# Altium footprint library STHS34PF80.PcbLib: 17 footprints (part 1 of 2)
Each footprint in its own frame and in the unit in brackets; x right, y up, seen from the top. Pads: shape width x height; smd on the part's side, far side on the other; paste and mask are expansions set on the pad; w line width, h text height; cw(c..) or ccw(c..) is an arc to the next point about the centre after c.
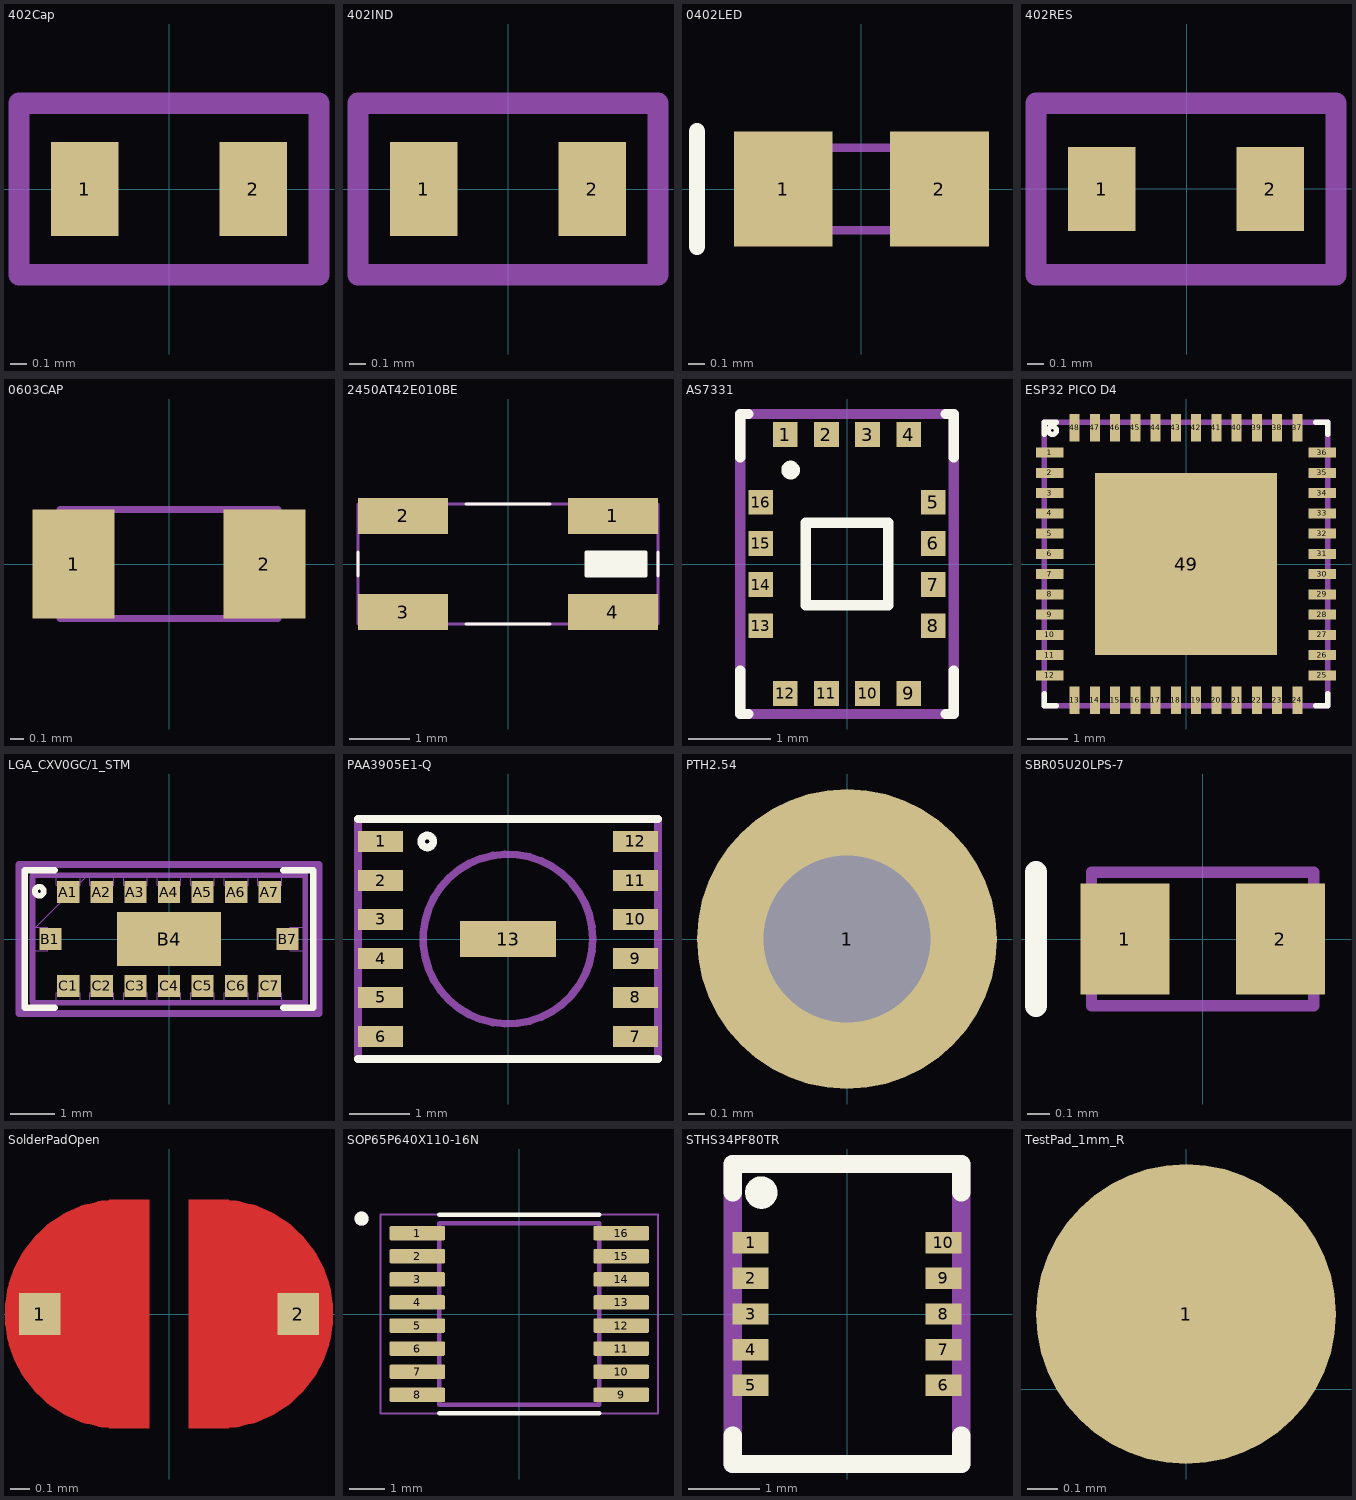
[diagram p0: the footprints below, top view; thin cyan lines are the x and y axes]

## 402Cap [mm] "0402 package capacitor"
pads (2):
  rect 0.4x0.559 smd: 1(-0.5,0) 2(0.5,0)
Mechanical 1:
  lines w0.127: -0.889,-0.508 0.889,-0.508 0.889,0.508 -0.889,0.508 -0.889,0.254 -0.889,-0.254 -0.889,-0.508
  text "'.Designator'" at -1.439,-0.106 h0.25
3D body "CAP_0402_N_WAL.step": height 0.58, standoff 0.01, extent -0.521,-0.279 0.521,0.279

## 402IND [mm] "0402 package for inductors"
pads (2):
  rect 0.4x0.559 smd: 1(-0.5,0) 2(0.5,0)
Mechanical 1:
  lines w0.127: -0.889,-0.508 0.889,-0.508 0.889,0.508 -0.889,0.508 -0.889,0.254 -0.889,-0.254 -0.889,-0.508
  text "'.Designator'" at -6.236,-0.628 h0.64
3D body "BLM15AX121SN1D.STEP": height 0.51, standoff 0.01, extent -0.5,-0.271 0.5,0.279

## 0402LED [mm] "0402 package size footprint for leds"
pads (2):
  rect 0.6x0.7 smd: 1(-0.475,0) 2(0.475,0)
Top Overlay:
  lines w0.1: -1,-0.35 -1,0.35
Mechanical 1:
  lines w0.051: -0.5,-0.25 -0.5,0.25 0.5,0.25 0.5,-0.25 -0.5,-0.25
  text "'.Designator'" at -3.75,-0.628 h0.64
3D body "VLMx15xx_0402.stp": height 0.32, standoff -0.03, extent -0.5,-0.25 0.5,0.25

## 402RES [mm] "0402 package resistor"
pads (2):
  rect 0.4x0.5 smd: 1(-0.504,-0.001) 2(0.496,-0.001)
Mechanical 1:
  lines w0.127: -0.893,-0.509 0.885,-0.509 0.885,0.507 -0.893,0.507 -0.893,0.253 -0.893,-0.255 -0.893,-0.509
  text "'.Designator'" at -1.488,-0.714 h0.25
3D body "RC0402FR-074K7P.STEP": height 0.41, standoff 0.01, extent -0.504,-0.251 0.496,0.249

## 0603CAP [mm] "0603 capacitor footprint"
pads (2):
  rect 0.6x0.8 smd mask+0.05: 1(-0.7,0) 2(0.7,0)
Mechanical 1:
  lines w0.051: -0.775,0.375 -0.8,0.4 ; 0.775,-0.375 0.8,-0.4 ; -0.8,0.4 -0.8,-0.4 0.8,-0.4 ; -0.8,0.4 0.8,0.4 0.8,-0.4
  text "'.Designator'" at -3.75,-0.628 h0.64
3D body "GRT188R61C106ME13D.STEP": height 0.8, standoff 0, extent -0.8,-0.4 0.8,0.4

## 2450AT42E010BE [mm] "2.4GHz Bluetooth, WLAN, Zigbee™ Chip RF Antenna 2.4GHz ~ 2.48GHz -2dBi Solder Surface Mount"
pads (4):
  rect 1.5x0.6 smd: 1(1.75,0.8) 2(-1.75,0.8) 3(-1.75,-0.8) 4(1.75,-0.8)
Top Overlay:
  region: 1.3,0.2 2.3,0.2 2.3,-0.2 1.3,-0.2
  lines w0.051: -2.5,-0.2 -2.5,0.2 ; -0.7,-1 0.7,-1 ; -0.7,1 0.7,1 ; 2.5,-0.2 2.5,0.2 ; 1.3,-0.2 1.3,0.2 2.3,0.2 2.3,-0.2 1.3,-0.2
Mechanical 1:
  lines w0.051: -2.5,-1 -2.5,1 2.5,1 2.5,-1 -2.5,-1
  text "'.Designator'" at -3.75,-0.628 h0.64
3D body "2450AT42E010BE--3DModel-STEP-56544.STEP": height 1.7, standoff 0, extent -2.5,-1 2.5,1

## AS7331 [mm] "Ambient Light Sensors AS7331 3channel UV-A/B/C spectral sensor IC"
pads (16):
  rect 0.3x0.3 smd: 1(-0.75,1.575) 2(-0.25,1.575) 3(0.25,1.575) 4(0.75,1.575) 5(1.05,0.75) 6(1.05,0.25) 7(1.05,-0.25) 8(1.05,-0.75) 9(0.75,-1.575) 10(0.25,-1.575) 11(-0.25,-1.575) 12(-0.75,-1.575) 13(-1.05,-0.75) 14(-1.05,-0.25) 15(-1.05,0.25) 16(-1.05,0.75)
Top Overlay:
  circle w0.127: c-0.686,1.143 r0.05
  lines w0.127: -1.3,-1.3 -1.3,-1.825 -1.2,-1.825 ; -1.3,1.3 -1.3,1.825 -1.2,1.825 ; 1.2,-1.825 1.3,-1.825 1.3,-1.3 ; 1.2,1.825 1.3,1.825 1.3,1.3 ; -0.5,-0.5 -0.5,0.5 0.5,0.5 0.5,-0.5 -0.5,-0.5
Mechanical 1:
  lines w0.127: -1.3,-1.825 -1.3,1.825 1.3,1.825 1.3,-1.825 -1.3,-1.825
  text ".Designator" at -3.809,-0.254 h0.76
3D body: height 1.09, standoff 0.1, extent -1.3,-1.825 1.3,1.825

## ESP32 PICO D4 [mm] "Bluetooth, WiFi 802.11b/g/n, Bluetooth v4.2 +EDR, Class 1, 2 and 3 Transceiver Module 2.4GHz ~ 2.5GHz Surface Mount"
pads (49):
  rect 0.68x0.25 smd: 1(-3.365,2.75) 2(-3.365,2.25) 3(-3.365,1.75) 4(-3.365,1.25) 5(-3.365,0.75) 6(-3.365,0.25) 7(-3.365,-0.25) 8(-3.365,-0.75) 9(-3.365,-1.25) 10(-3.365,-1.75) 11(-3.365,-2.25) 12(-3.365,-2.75) 25(3.365,-2.75) 26(3.365,-2.25) 27(3.365,-1.75) 28(3.365,-1.25) 29(3.365,-0.75) 30(3.365,-0.25) 31(3.365,0.25) 32(3.365,0.75) 33(3.365,1.25) 34(3.365,1.75) 35(3.365,2.25) 36(3.365,2.75)
  rect 0.25x0.68 smd: 13(-2.75,-3.365) 14(-2.25,-3.365) 15(-1.75,-3.365) 16(-1.25,-3.365) 17(-0.75,-3.365) 18(-0.25,-3.365) 19(0.25,-3.365) 20(0.75,-3.365) 21(1.25,-3.365) 22(1.75,-3.365) 23(2.25,-3.365) 24(2.75,-3.365) 37(2.75,3.365) 38(2.25,3.365) 39(1.75,3.365) 40(1.25,3.365) 41(0.75,3.365) 42(0.25,3.365) 43(-0.25,3.365) 44(-0.75,3.365) 45(-1.25,3.365) 46(-1.75,3.365) 47(-2.25,3.365) 48(-2.75,3.365)
  rect 4.5x4.5 smd: 49(0,0)
Top Overlay:
  circle w0.127: c-3.3,3.3 r0.1
  lines w0.127: -3.5,-3.2 -3.5,-3.5 -3.2,-3.5 ; -3.5,3.2 -3.5,3.5 -3.2,3.5 ; 3.2,-3.5 3.5,-3.5 3.5,-3.2 ; 3.2,3.5 3.5,3.5 3.5,3.2
Mechanical 1:
  lines w0.127: -3.5,-3.5 -3.5,3.5 3.5,3.5 3.5,-3.5 -3.5,-3.5
  text "'.Designator'" at -3.81,-0.628 h0.64
3D body "ESP32-PICO-D4--3DModel-STEP-56544.STEP": height 1.05, standoff 0.01, extent -3.5,-3.5 3.5,3.5

## LGA_CXV0GC/1_STM [mm]
pads (17):
  rect 0.5x0.5 smd: A1(-2.25,1.05) A2(-1.5,1.05) A3(-0.75,1.05) A4(0,1.05) A5(0.75,1.05) A6(1.5,1.05) A7(2.25,1.05) B1(-2.65,0) B7(2.65,0) C1(-2.25,-1.05) C2(-1.5,-1.05) C3(-0.75,-1.05) C4(0,-1.05) C5(0.75,-1.05) C6(1.5,-1.05) C7(2.25,-1.05)
  rect 2.316x1.2 smd: B4(0,0)
Top Overlay:
  circle w0.127: c-2.9,1.067 r0.1
  lines w0.152: -2.558,-1.537 -3.226,-1.537 -3.226,1.537 -2.558,1.537 ; 2.558,-1.537 3.226,-1.537 3.226,1.537 2.558,1.537
Mechanical 1:
  lines w0.127: -3.048,-1.422 3.048,-1.422 3.048,1.422 -3.048,1.422 -3.048,1.346 -3.048,-1.372
Mechanical 13:
  lines w0.025: -3.099,0.14 -1.829,1.41 ; -3.099,-1.41 3.099,-1.41 3.099,1.41 -3.099,1.41 -3.099,-1.41 ; -3.099,-0.267 -3.099,0.267 -2.705,0.267 -2.705,-0.267 -3.099,-0.267 ; -2.517,-1.41 -1.983,-1.41 -1.983,-1.206 -2.517,-1.206 -2.517,-1.41 ; -2.517,1.206 -1.983,1.206 -1.983,1.41 -2.517,1.41 -2.517,1.206 ; -1.767,-1.41 -1.233,-1.41 -1.233,-1.206 -1.767,-1.206 -1.767,-1.41 ; -1.767,1.206 -1.233,1.206 -1.233,1.41 -1.767,1.41 -1.767,1.206 ; -1.017,-1.41 -0.483,-1.41 -0.483,-1.206 -1.017,-1.206 -1.017,-1.41 ; -1.017,1.206 -0.483,1.206 -0.483,1.41 -1.017,1.41 -1.017,1.206 ; -0.267,-1.41 0.267,-1.41 0.267,-1.206 -0.267,-1.206 -0.267,-1.41 ; -0.267,1.206 0.267,1.206 0.267,1.41 -0.267,1.41 -0.267,1.206 ; 0.483,-1.41 1.017,-1.41 1.017,-1.206 0.483,-1.206 0.483,-1.41 ; 0.483,1.206 1.017,1.206 1.017,1.41 0.483,1.41 0.483,1.206 ; 1.233,-1.41 1.767,-1.41 1.767,-1.206 1.233,-1.206 1.233,-1.41 ; 1.233,1.206 1.767,1.206 1.767,1.41 1.233,1.41 1.233,1.206 ; 1.983,-1.41 2.517,-1.41 2.517,-1.206 1.983,-1.206 1.983,-1.41 ; 1.983,1.206 2.517,1.206 2.517,1.41 1.983,1.41 1.983,1.206 ; 2.705,-0.267 3.099,-0.267 3.099,0.267 2.705,0.267 2.705,-0.267
Mechanical 15:
  lines w0.152: -3.353,-1.664 -3.353,-0.521 -3.353,0.521 -3.353,1.664 -2.771,1.664 2.771,1.664 3.353,1.664 3.353,0.521 3.353,-0.521 3.353,-1.664 2.771,-1.664 -2.771,-1.664 -3.353,-1.664
3D body "VL53L5CX_3D_model.step": height 3.59, standoff 0.02, extent -3.598,-1.515 3.208,1.584
3D body: height 0.25, standoff 0, extent 0,0 0.254,0.254

## PAA3905E1-Q [mm] "PixArt Imaging's optical motion  tracking chip s"
pads (13):
  rect 0.75x0.35 smd: 1(-2.125,1.625) 2(-2.125,0.975) 3(-2.125,0.325) 4(-2.125,-0.325) 5(-2.125,-0.975) 6(-2.125,-1.625) 7(2.125,-1.625) 8(2.125,-0.975) 9(2.125,-0.325) 10(2.125,0.325) 11(2.125,0.975) 12(2.125,1.625)
  rect 1.6x0.6 smd: 13(0,0)
Top Overlay:
  circle w0.127: c-1.346,1.626 r0.1
  lines w0.127: -2.5,-2 2.5,-2 ; -2.5,2 2.5,2
Mechanical 1:
  circle w0.127: c0,0 r1.414
  lines w0.127: -2.5,-2 -2.5,2 2.5,2 2.5,-2 -2.5,-2
  text ".Designator" at -4.998,-0.333 h1
3D body "PAA3905_Assembly.STEP": height 3.03, standoff 0.03, extent -2.5,-2 2.5,2

## PTH2.54 [mm] "Standard 0.1\" plated through hole"
pads (1):
  round 1.8 hole 1: 1(0,0)

## SBR05U20LPS-7 [mm] "Diode Super Barrier 20 V 500mA Surface Mount DFN1006H4-2"
pads (2):
  rect 0.4x0.5 smd: 1(-0.35,0) 2(0.35,0)
Top Overlay:
  lines w0.1: -0.75,-0.3 -0.75,0.3
Mechanical 1:
  lines w0.051: 0.4,0.3 -0.5,0.3 ; -0.5,0.3 0.5,0.3 0.5,-0.3 -0.5,-0.3 -0.5,0.3
  text "'.Designator'" at -3.75,-0.628 h0.64
3D body "DFN1006H4-2.stp": height 0.4, standoff 0, extent -0.5,-0.3 0.5,0.3

## SolderPadOpen [mm]
pads (2):
  rect 0.21x0.21 smd: 1(-0.65,0) 2(0.65,0)
Top Layer:
  region: 0.1,-0.575 0.1,0.575 0.3,0.575 0.711,0.127 0.711,-0.229 0.686,-0.229 0.3,-0.575
  region: -0.1,0.575 -0.1,-0.575 -0.3,-0.575 -0.711,-0.127 -0.711,0.229 -0.686,0.229 -0.3,0.575
  lines w0.254: -0.25,-0.45 cw(c-0.25,0) -0.25,0.45 ; 0.25,-0.45 ccw(c0.25,0) 0.25,0.45
Top Solder:
  circle w0.5: c0.25,0 r0.4
  circle w0.5: c-0.25,0 r0.4

## SOP65P640X110-16N [mm]
pads (16):
  rrect25% 1.57x0.41 smd: 1(-2.87,2.275) 2(-2.87,1.625) 3(-2.87,0.975) 4(-2.87,0.325) 5(-2.87,-0.325) 6(-2.87,-0.975) 7(-2.87,-1.625) 8(-2.87,-2.275) 9(2.87,-2.275) 10(2.87,-1.625) 11(2.87,-0.975) 12(2.87,-0.325) 13(2.87,0.325) 14(2.87,0.975) 15(2.87,1.625) 16(2.87,2.275)
Top Overlay:
  circle w0.2: c-4.44,2.685 r0.1
  lines w0.127: -2.25,-2.8 2.25,-2.8 ; -2.25,2.8 2.25,2.8
Mechanical 1:
  text ".Designator" at -4.998,-0.333 h1
Mechanical 13:
  circle w0.2: c-4.44,2.685 r0.1
  lines w0.127: -2.25,-2.55 -2.25,2.55 2.25,2.55 2.25,-2.55 -2.25,-2.55
Mechanical 15:
  lines w0.05: -3.905,-2.8 -3.905,2.8 3.905,2.8 3.905,-2.8 -3.905,-2.8
3D body "S8HP--3DModel-STEP-56544.STEP": height 1.11, standoff 0.01, extent -3.2,-2.5 3.2,2.5

## STHS34PF80TR [mm] "OLGA-10L 3.2 x 4.2 x 1.455 mm package"
pads (10):
  rect 0.5x0.3 smd: 1(-1.35,1) 2(-1.35,0.5) 3(-1.35,0) 4(-1.35,-0.5) 5(-1.35,-1) 6(1.35,-1) 7(1.35,-0.5) 8(1.35,0) 9(1.35,0.5) 10(1.35,1)
Top Overlay:
  circle w0.254: c-1.2,1.7 r0.1
  lines w0.254: -1.6,-1.7 -1.6,-2.1 1.6,-2.1 1.6,-1.7 ; -1.6,1.7 -1.6,2.1 1.6,2.1 1.6,1.7
Mechanical 1:
  lines w0.254: -1.6,-2.1 1.6,-2.1 1.6,2.1 -1.6,2.1 -1.6,-2.1
  text ".Designator" at 0.104,-2.539 h0.51
3D body: height 1.5, standoff 0.05, extent -1.6,-2.1 1.6,2.1

## TestPad_1mm_R [mm]
pads (1):
  round 1 smd: 1(0,0.25)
